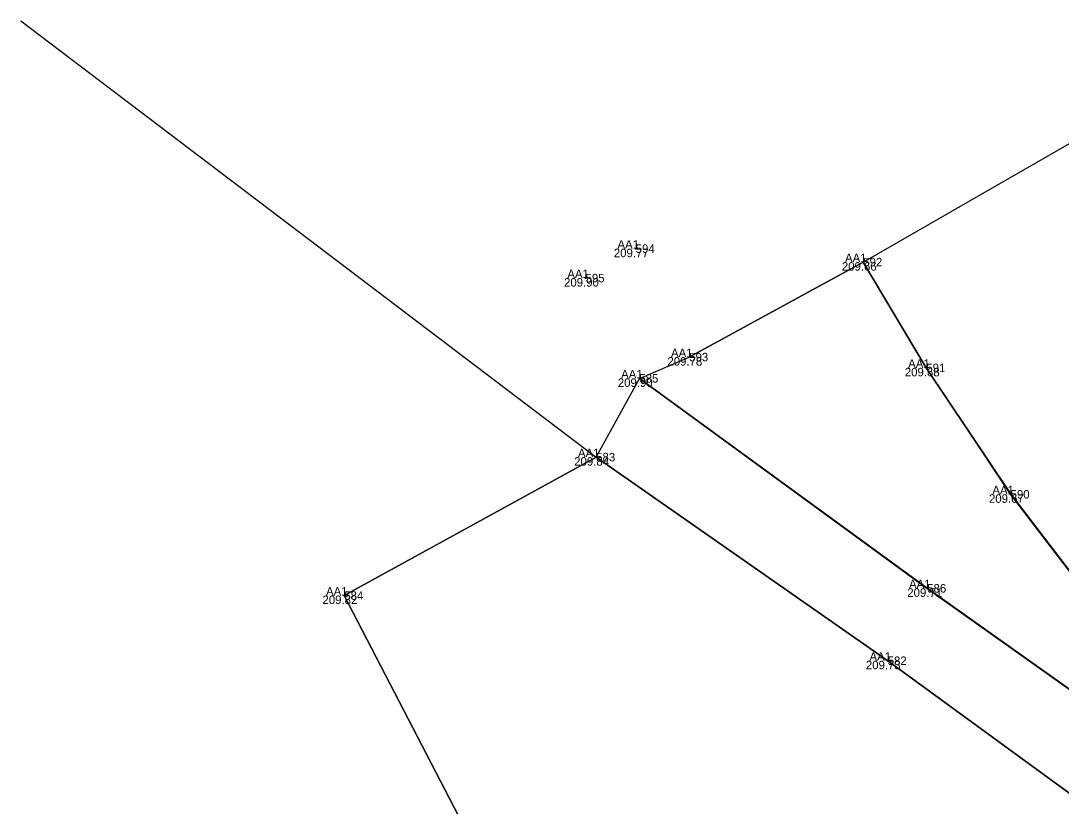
# Model space of a CAD drawing. Extents: x -262982 to -262706, y -1238714 to -1237093.
# Drawn here: x -262982.43 to -262957.98, y -1238394.45 to -1238375.98 of the extents above; entities that cross this region are included whole.
import ezdxf

# ---------------------------------------------------------------- set-up
doc = ezdxf.new("R2010")
doc.units = 0
for name, color, linetype in [('03_Asfalt', 7, 'Continuous'), ('10', 7, 'Continuous'), ('Groma (21)', 7, 'Continuous'), ('Groma (22)', 7, 'Continuous'), ('Groma (23)', 7, 'Continuous'), ('Groma (24)', 7, 'Continuous'), ('U001_Zeleň_mimo', 7, 'Continuous'), ('U002_Asfalt', 7, 'Continuous'), ('U002_Zeleň_mimo', 7, 'Continuous')]:
    doc.layers.add(name, color=color, linetype=linetype)

msp = doc.modelspace()

# ---------------------------------------------------------------- linework, layer by layer
at = {"layer": '03_Asfalt'}
for points in [[(-262967.893, -1238384.386), (-262961.125, -1238389.323), (-262954.307, -1238394.16), (-262953.782, -1238393.748), (-262956.194, -1238390.986), (-262959.165, -1238387.112), (-262961.145, -1238384.138), (-262962.629, -1238381.652), (-262966.72, -1238383.885)], [(-262954.673, -1238396.412), (-262962.054, -1238391.026), (-262968.907, -1238386.238), (-262974.83, -1238389.493)], [(-262974.83, -1238389.493), (-262966.434, -1238405.689)]]:
    msp.add_lwpolyline(points, dxfattribs=at)
at = {"layer": '10'}
msp.add_lwpolyline([(-262982.434, -1238375.977), (-262968.907, -1238386.238), (-262962.054, -1238391.026), (-262954.673, -1238396.412), (-262941.774, -1238405.784), (-262928.896, -1238415.327), (-262917.716, -1238423.993), (-262905.824, -1238433.621), (-262895.067, -1238441.663), (-262870.407, -1238460.6)], dxfattribs=at)
at = {"layer": 'Groma (21)'}
for centre in [(-262967.979, -1238381.336), (-262962.629, -1238381.652), (-262969.157, -1238382.027), (-262966.72, -1238383.885), (-262961.145, -1238384.138), (-262967.893, -1238384.386), (-262968.907, -1238386.238), (-262959.165, -1238387.112), (-262961.125, -1238389.323), (-262974.83, -1238389.493), (-262962.054, -1238391.026)]:
    msp.add_circle(centre, 0.01, dxfattribs=at)
at = {"layer": 'U001_Zeleň_mimo'}
msp.add_lwpolyline([(-262966.43, -1238405.69), (-262974.83, -1238389.49), (-262968.91, -1238386.24), (-262962.05, -1238391.03), (-262954.67, -1238396.41)], dxfattribs=at)
msp.add_lwpolyline([(-262966.43, -1238405.69), (-262974.83, -1238389.49), (-262968.91, -1238386.24), (-262962.05, -1238391.03), (-262954.67, -1238396.41)], dxfattribs=at)
at = {"layer": 'U002_Asfalt'}
for points in [[(-262956.19, -1238390.99), (-262959.16, -1238387.11), (-262961.15, -1238384.14), (-262962.63, -1238381.65), (-262956.048, -1238377.869)], [(-262954.67, -1238396.41), (-262962.05, -1238391.03), (-262968.91, -1238386.24), (-262967.89, -1238384.39), (-262961.13, -1238389.32), (-262954.31, -1238394.16)]]:
    msp.add_lwpolyline(points, dxfattribs=at)
at = {"layer": 'U002_Zeleň_mimo'}
msp.add_lwpolyline([(-262961.15, -1238384.14), (-262959.16, -1238387.11), (-262956.19, -1238390.99), (-262953.78, -1238393.75), (-262954.31, -1238394.16), (-262961.13, -1238389.32), (-262967.89, -1238384.39), (-262966.72, -1238383.89), (-262962.63, -1238381.65)], close=True, dxfattribs=at)

# ---------------------------------------------------------------- texts
at = {"layer": 'Groma (22)'}
for s, p in [('594', (-262967.979, -1238381.436)), ('592', (-262962.629, -1238381.752)), ('595', (-262969.157, -1238382.127)), ('593', (-262966.72, -1238383.985)), ('591', (-262961.145, -1238384.238)), ('585', (-262967.893, -1238384.486)), ('583', (-262968.907, -1238386.338)), ('590', (-262959.165, -1238387.212)), ('586', (-262961.125, -1238389.423)), ('584', (-262974.83, -1238389.593)), ('582', (-262962.054, -1238391.126))]:
    msp.add_text(s, height=0.2, dxfattribs=at).set_placement(p)
at = {"layer": 'Groma (23)'}
for s, p in [('209.77', (-262968.492, -1238381.536)), ('209.66', (-262963.131, -1238381.852)), ('209.90', (-262969.663, -1238382.227)), ('209.78', (-262967.233, -1238384.085)), ('209.68', (-262961.652, -1238384.338)), ('209.90', (-262968.399, -1238384.586)), ('209.84', (-262969.424, -1238386.438)), ('209.67', (-262959.673, -1238387.312)), ('209.71', (-262961.594, -1238389.523)), ('209.82', (-262975.342, -1238389.693)), ('209.73', (-262962.567, -1238391.226))]:
    msp.add_text(s, height=0.2, dxfattribs=at).set_placement(p)
at = {"layer": 'Groma (24)'}
for p in [(-262968.407, -1238381.336), (-262963.057, -1238381.652), (-262969.585, -1238382.027), (-262967.148, -1238383.885), (-262961.573, -1238384.138), (-262968.321, -1238384.386), (-262969.335, -1238386.238), (-262959.593, -1238387.112), (-262961.553, -1238389.323), (-262975.258, -1238389.493), (-262962.482, -1238391.026)]:
    msp.add_text('AA1', height=0.2, dxfattribs=at).set_placement(p)

doc.saveas('drawing.dxf')
